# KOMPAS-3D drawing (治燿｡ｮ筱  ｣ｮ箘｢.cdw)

Views: Вид 1
Referenced files in C:\Program Files\ASCON\KOMPAS-3D V10\Libs\: Tech.lfr|Устройства установочные|Оправка цилиндрическая, Tech.lfr, Tech.lfr|Формы поверхности|Ромбическая
Referenced files in C:\Program Files\ASCON\KOMPAS-3D V11\Sys\: GRAPHIC.LHS
Referenced files: план.cdw
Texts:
  ТМ-27А. КП.
  План  изготовления
  Логинов
  Текст на чертеже
  Размерные надписи
  Шероховатость
  Линия-выноска #1
  Линия-выноска #2
  Линия-выноска #3
  Отклонения формы и база
  Заголовок таблицы
  Ячейка таблицы
  Стрелка вида
  Обозначение изменения
  Фигурная скобка
  Номер узла
  Марка координационной оси
  VRCB
  Выносная надпись
  Обозначение узла
  Марка/позиционное обозначение с линией-выноской
  Марка/позиционное обозначение на линии
  Марка/позиционное обозначение без линии-выноски
  Устройства установочные|Оправка цилиндрическая
  Формы поверхности|Ромбическая
  Оправка цилиндрическая
  Ромбическая
  Normal
  КГШП
  Ra 6,3
  010 Комбинированная с ЧПУ
  Установ А
  Установ Б
  Ra 3,2
  Ra 5
  "Хурт"
  Ra 1,6
  045 Торцекругошлифовальная
  Rz200
  Ra 12,5
  Камерная моечная
  машина
  Промыть, обдуть, просушить горячим
  воздухом
  Контрольный
  стенд
  Контролировать параметры детали
  согласно чертежу
  РХ1
  РХ2
  РХ3
  РХ4
  РХ5
  РХ6
  Рабочий ход
  инструмента
  Стили документа
  План
  изготовления
  Технологический процесс
  изготовления первичного
  вала раздаточной коробки
  НТУ ХПИ
  каф. А и Т
  КП 09. 151001. 21. ПИ-
  Павлий
Dimensions and other numbers on the sheet: 7; 005 Заготовительная; 1К341Ф3; 16К20Ф3; 015 Токарная; 020 Токарная; 025 Фрезерная; 030 Фрезерная; 040 Центрошлифовальная; 3922; 36153Т; 1; 5; 6; 9; 3; 4; 2O з; 2Р з; 2; 050 Шлицешлифовальная; 040 Термическая; 055 Моечная; 060 Контрольная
